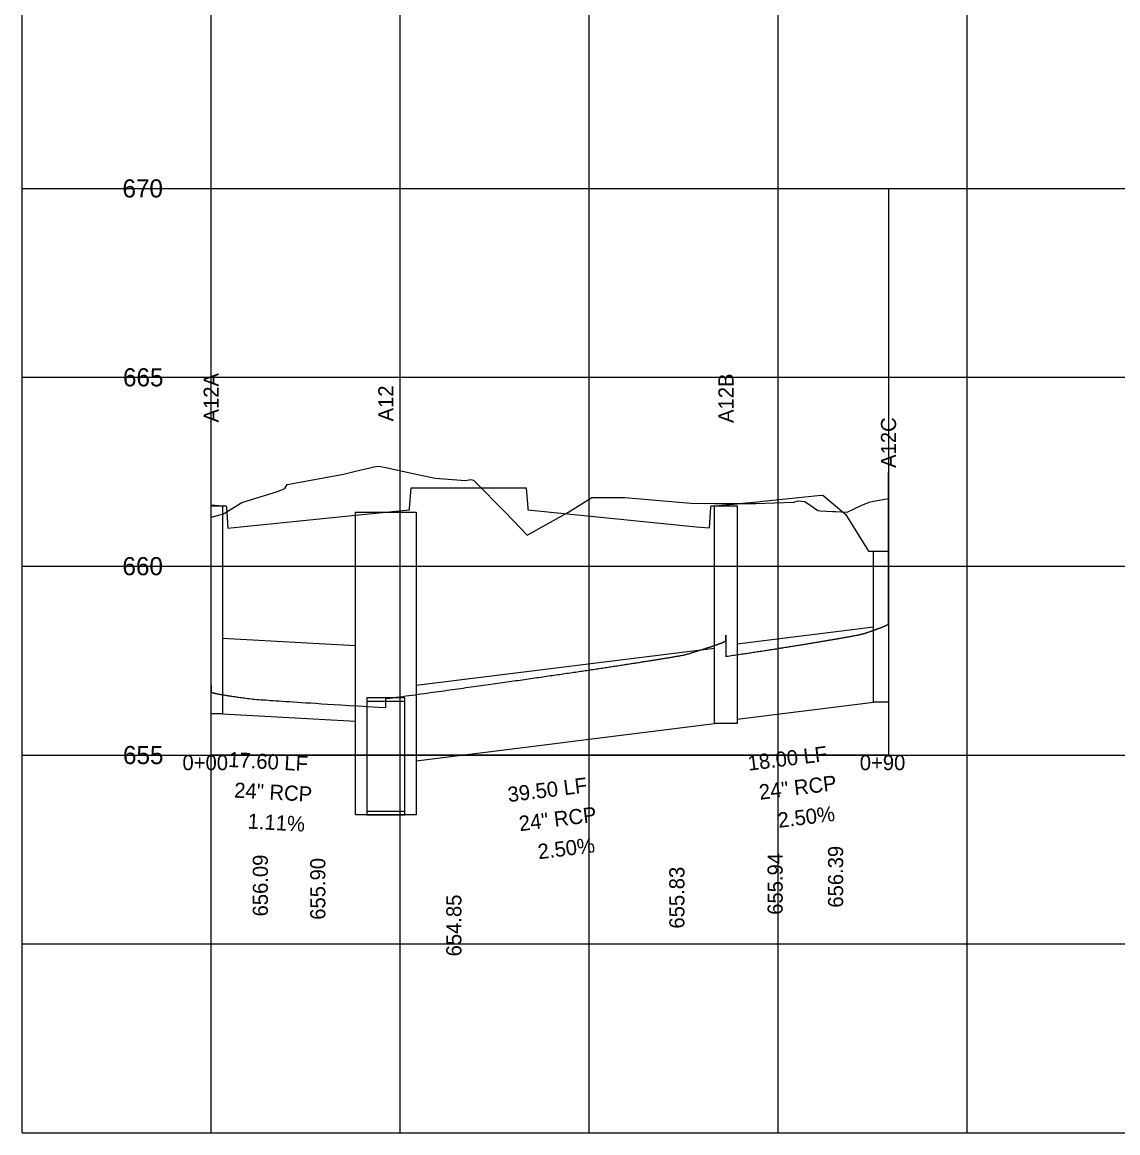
# Model space of a CAD drawing. Extents: x 2252703 to 2264864, y 13787568 to 13790989.
# Drawn here: x 2264413.7 to 2264558.6, y 13789015.9 to 13789162.9 of the extents above; entities that cross this region are included whole.
import ezdxf

# ---------------------------------------------------------------- set-up
doc = ezdxf.new("R2010")
doc.units = 0
for name, color, linetype in [('blank4', 7, 'Continuous'), ('BORD_grid_bottom_major_5int', 7, 'Continuous'), ('D_DRN_PROF_HGL', 7, 'Continuous'), ('D_PROF_1', 7, 'Continuous'), ('D_PROF_NOTES_1', 7, 'Continuous'), ('Default', 7, 'Continuous'), ('Drain_PipeInside', 7, 'Continuous'), ('E_Terrain', 7, 'Continuous'), ('Inlet', 7, 'Continuous'), ('z - Construction', 7, 'Continuous')]:
    doc.layers.add(name, color=color, linetype=linetype)

msp = doc.modelspace()

# ---------------------------------------------------------------- linework, layer by layer
at = {"layer": 'blank4'}
msp.add_lwpolyline([(2264438.67, 13789065.93), (2264438.67, 13789140.93), (2264528.27, 13789140.93), (2264528.27, 13789065.93)], close=True, dxfattribs=at)
at = {"layer": 'BORD_grid_bottom_major_5int'}
for p, q in [((2264413.67, 13789015.93), (2264413.67, 13789315.93)), ((2264438.67, 13789015.93), (2264438.67, 13789315.93)), ((2264463.67, 13789015.93), (2264463.67, 13789315.93)), ((2264488.67, 13789015.93), (2264488.67, 13789315.93)), ((2264513.67, 13789015.93), (2264513.67, 13789315.93)), ((2264538.67, 13789015.93), (2264538.67, 13789315.93)), ((2264413.67, 13789140.93), (2264763.67, 13789140.93)), ((2264413.67, 13789115.93), (2264763.67, 13789115.93)), ((2264413.67, 13789090.93), (2264763.67, 13789090.93)), ((2264413.67, 13789065.93), (2264763.67, 13789065.93)), ((2264413.67, 13789040.93), (2264763.67, 13789040.93)), ((2264413.67, 13789015.93), (2264763.67, 13789015.93))]:
    msp.add_line(p, q, dxfattribs=at)
at = {"layer": 'D_DRN_PROF_HGL'}
for p, q in [((2264506.77, 13789081.82), (2264506.77, 13789078.99)), ((2264461.77, 13789072.22), (2264461.77, 13789073.39))]:
    msp.add_line(p, q, dxfattribs=at)
for points in [[(2264506.77, 13789078.99), (2264506.85, 13789079), (2264507.06, 13789079.03), (2264507.27, 13789079.07), (2264507.47, 13789079.1), (2264507.68, 13789079.13), (2264507.88, 13789079.16), (2264508.09, 13789079.19), (2264508.29, 13789079.22), (2264508.48, 13789079.25), (2264508.68, 13789079.28), (2264508.88, 13789079.31), (2264509.07, 13789079.34), (2264509.27, 13789079.37), (2264509.46, 13789079.39), (2264509.65, 13789079.42), (2264509.84, 13789079.45), (2264510.02, 13789079.48), (2264510.21, 13789079.51), (2264510.4, 13789079.54), (2264510.58, 13789079.56), (2264510.76, 13789079.59), (2264510.94, 13789079.62), (2264511.12, 13789079.65), (2264511.3, 13789079.67), (2264511.48, 13789079.7), (2264511.65, 13789079.73), (2264511.82, 13789079.76), (2264512, 13789079.78), (2264512.17, 13789079.81), (2264512.34, 13789079.83), (2264512.51, 13789079.86), (2264512.68, 13789079.89), (2264512.84, 13789079.91), (2264513.01, 13789079.94), (2264513.17, 13789079.96), (2264513.33, 13789079.99), (2264513.5, 13789080.01), (2264513.66, 13789080.04), (2264513.81, 13789080.06), (2264513.97, 13789080.09), (2264514.13, 13789080.11), (2264514.28, 13789080.14), (2264514.44, 13789080.16), (2264514.59, 13789080.19), (2264514.74, 13789080.21), (2264514.9, 13789080.23), (2264515.05, 13789080.26), (2264515.19, 13789080.28), (2264515.34, 13789080.31), (2264515.49, 13789080.33), (2264515.63, 13789080.35), (2264515.78, 13789080.37), (2264515.92, 13789080.4), (2264516.06, 13789080.42), (2264516.2, 13789080.44), (2264516.34, 13789080.47), (2264516.48, 13789080.49), (2264516.62, 13789080.51), (2264516.76, 13789080.53), (2264516.89, 13789080.55), (2264517.03, 13789080.58), (2264517.16, 13789080.6), (2264517.29, 13789080.62), (2264517.43, 13789080.64), (2264517.56, 13789080.66), (2264517.69, 13789080.68), (2264517.81, 13789080.7), (2264517.94, 13789080.73), (2264518.07, 13789080.75), (2264518.19, 13789080.77), (2264518.32, 13789080.79), (2264518.44, 13789080.81), (2264518.57, 13789080.83), (2264518.69, 13789080.85), (2264518.81, 13789080.87), (2264518.93, 13789080.89), (2264519.05, 13789080.91), (2264519.17, 13789080.93), (2264519.28, 13789080.95), (2264519.4, 13789080.97), (2264519.51, 13789080.99), (2264519.63, 13789081.01), (2264519.74, 13789081.03), (2264519.85, 13789081.04), (2264519.97, 13789081.06), (2264520.08, 13789081.08), (2264520.19, 13789081.1), (2264520.3, 13789081.12), (2264520.4, 13789081.14), (2264520.51, 13789081.16), (2264520.62, 13789081.17), (2264520.72, 13789081.19), (2264520.83, 13789081.21), (2264520.93, 13789081.23), (2264521.03, 13789081.25), (2264521.14, 13789081.26), (2264521.24, 13789081.28), (2264521.34, 13789081.3), (2264521.44, 13789081.32), (2264521.54, 13789081.33), (2264521.63, 13789081.35), (2264521.73, 13789081.37), (2264521.83, 13789081.39), (2264521.92, 13789081.4), (2264522.02, 13789081.42), (2264522.11, 13789081.44), (2264522.2, 13789081.45), (2264522.29, 13789081.47), (2264522.39, 13789081.49), (2264522.48, 13789081.5), (2264522.57, 13789081.52), (2264522.66, 13789081.53), (2264522.74, 13789081.55), (2264522.83, 13789081.57), (2264522.92, 13789081.58), (2264523, 13789081.6), (2264523.09, 13789081.61), (2264523.17, 13789081.63), (2264523.26, 13789081.64), (2264523.34, 13789081.66), (2264523.42, 13789081.67), (2264523.5, 13789081.69), (2264523.58, 13789081.71), (2264523.66, 13789081.72), (2264523.74, 13789081.74), (2264523.82, 13789081.75), (2264523.9, 13789081.76), (2264523.97, 13789081.78), (2264524.05, 13789081.79), (2264524.12, 13789081.81), (2264524.2, 13789081.82), (2264524.27, 13789081.84), (2264524.35, 13789081.85), (2264524.42, 13789081.86), (2264524.49, 13789081.88), (2264524.56, 13789081.89), (2264524.63, 13789081.91), (2264524.7, 13789081.92), (2264524.77, 13789081.93), (2264524.84, 13789081.96), (2264524.9, 13789081.98), (2264524.97, 13789082), (2264525.04, 13789082.02), (2264525.1, 13789082.04), (2264525.17, 13789082.06), (2264525.23, 13789082.08), (2264525.29, 13789082.1), (2264525.36, 13789082.12), (2264525.42, 13789082.15), (2264525.48, 13789082.17), (2264525.54, 13789082.19), (2264525.6, 13789082.21), (2264525.66, 13789082.23), (2264525.72, 13789082.24), (2264525.77, 13789082.26), (2264525.83, 13789082.28), (2264525.89, 13789082.3), (2264525.94, 13789082.32), (2264526, 13789082.34), (2264526.05, 13789082.36), (2264526.1, 13789082.38), (2264526.16, 13789082.4), (2264526.21, 13789082.41), (2264526.26, 13789082.43), (2264526.31, 13789082.45), (2264526.36, 13789082.47), (2264526.41, 13789082.48), (2264526.46, 13789082.5), (2264526.51, 13789082.52), (2264526.56, 13789082.53), (2264526.6, 13789082.55), (2264526.65, 13789082.57), (2264526.7, 13789082.58), (2264526.74, 13789082.6), (2264526.78, 13789082.62), (2264526.83, 13789082.63), (2264526.87, 13789082.65), (2264526.91, 13789082.66), (2264526.95, 13789082.68), (2264527, 13789082.69), (2264527.04, 13789082.71), (2264527.08, 13789082.72), (2264527.12, 13789082.74), (2264527.15, 13789082.75), (2264527.19, 13789082.77), (2264527.23, 13789082.78), (2264527.26, 13789082.8), (2264527.3, 13789082.81), (2264527.34, 13789082.82), (2264527.37, 13789082.84), (2264527.4, 13789082.85), (2264527.44, 13789082.87), (2264527.47, 13789082.88), (2264527.5, 13789082.89), (2264527.53, 13789082.9), (2264527.56, 13789082.92), (2264527.59, 13789082.93), (2264527.62, 13789082.94), (2264527.65, 13789082.95), (2264527.68, 13789082.97), (2264527.71, 13789082.98), (2264527.74, 13789082.99), (2264527.76, 13789083), (2264527.79, 13789083.01), (2264527.81, 13789083.02), (2264527.84, 13789083.03), (2264527.86, 13789083.05), (2264527.88, 13789083.06), (2264527.9, 13789083.07), (2264527.93, 13789083.08), (2264527.95, 13789083.09), (2264527.97, 13789083.1), (2264527.99, 13789083.11), (2264528.01, 13789083.12), (2264528.03, 13789083.13), (2264528.04, 13789083.14), (2264528.06, 13789083.15), (2264528.08, 13789083.15), (2264528.09, 13789083.16), (2264528.11, 13789083.17), (2264528.12, 13789083.18), (2264528.14, 13789083.19), (2264528.15, 13789083.2), (2264528.16, 13789083.21), (2264528.17, 13789083.21), (2264528.18, 13789083.22), (2264528.2, 13789083.23), (2264528.21, 13789083.24), (2264528.21, 13789083.24), (2264528.22, 13789083.25), (2264528.23, 13789083.26), (2264528.24, 13789083.27), (2264528.24, 13789083.27), (2264528.25, 13789083.28), (2264528.26, 13789083.28), (2264528.26, 13789083.29), (2264528.26, 13789083.3), (2264528.27, 13789083.3), (2264528.27, 13789083.31), (2264528.27, 13789083.31), (2264528.27, 13789083.32), (2264528.27, 13789083.32), (2264528.27, 13789103.33)], [(2264461.77, 13789073.39), (2264461.84, 13789073.4), (2264462.28, 13789073.46), (2264462.72, 13789073.52), (2264463.15, 13789073.58), (2264463.57, 13789073.64), (2264464, 13789073.69), (2264464.41, 13789073.75), (2264464.83, 13789073.81), (2264465.24, 13789073.86), (2264465.64, 13789073.92), (2264466.05, 13789073.97), (2264466.45, 13789074.03), (2264466.84, 13789074.08), (2264467.23, 13789074.14), (2264467.62, 13789074.19), (2264468, 13789074.24), (2264468.39, 13789074.3), (2264468.76, 13789074.35), (2264469.14, 13789074.4), (2264469.51, 13789074.45), (2264469.88, 13789074.5), (2264470.24, 13789074.55), (2264470.6, 13789074.6), (2264470.96, 13789074.65), (2264471.31, 13789074.7), (2264471.67, 13789074.75), (2264472.01, 13789074.8), (2264472.36, 13789074.85), (2264472.7, 13789074.9), (2264473.04, 13789074.94), (2264473.38, 13789074.99), (2264473.71, 13789075.04), (2264474.04, 13789075.08), (2264474.37, 13789075.13), (2264474.7, 13789075.18), (2264475.02, 13789075.22), (2264475.34, 13789075.27), (2264475.65, 13789075.31), (2264475.97, 13789075.35), (2264476.28, 13789075.4), (2264476.59, 13789075.44), (2264476.9, 13789075.49), (2264477.2, 13789075.53), (2264477.5, 13789075.57), (2264477.8, 13789075.61), (2264478.1, 13789075.66), (2264478.39, 13789075.7), (2264478.68, 13789075.74), (2264478.97, 13789075.78), (2264479.26, 13789075.82), (2264479.54, 13789075.86), (2264479.82, 13789075.9), (2264480.1, 13789075.94), (2264480.38, 13789075.98), (2264480.65, 13789076.02), (2264480.93, 13789076.06), (2264481.2, 13789076.1), (2264481.46, 13789076.14), (2264481.73, 13789076.18), (2264481.99, 13789076.21), (2264482.26, 13789076.25), (2264482.52, 13789076.29), (2264482.77, 13789076.33), (2264483.03, 13789076.36), (2264483.28, 13789076.4), (2264483.53, 13789076.44), (2264483.78, 13789076.47), (2264484.03, 13789076.51), (2264484.28, 13789076.54), (2264484.52, 13789076.58), (2264484.76, 13789076.61), (2264485, 13789076.65), (2264485.24, 13789076.68), (2264485.47, 13789076.72), (2264485.71, 13789076.75), (2264485.94, 13789076.79), (2264486.17, 13789076.82), (2264486.4, 13789076.85), (2264486.62, 13789076.89), (2264486.85, 13789076.92), (2264487.07, 13789076.95), (2264487.29, 13789076.99), (2264487.51, 13789077.02), (2264487.73, 13789077.05), (2264487.94, 13789077.08), (2264488.16, 13789077.11), (2264488.37, 13789077.14), (2264488.58, 13789077.18), (2264488.79, 13789077.21), (2264489, 13789077.24), (2264489.2, 13789077.27), (2264489.41, 13789077.3), (2264489.61, 13789077.33), (2264489.81, 13789077.36), (2264490.01, 13789077.39), (2264490.21, 13789077.42), (2264490.4, 13789077.45), (2264490.6, 13789077.48), (2264490.79, 13789077.51), (2264490.98, 13789077.54), (2264491.17, 13789077.56), (2264491.36, 13789077.59), (2264491.54, 13789077.62), (2264491.73, 13789077.65), (2264491.91, 13789077.68), (2264492.1, 13789077.71), (2264492.28, 13789077.73), (2264492.46, 13789077.76), (2264492.63, 13789077.79), (2264492.81, 13789077.81), (2264492.99, 13789077.84), (2264493.16, 13789077.87), (2264493.33, 13789077.9), (2264493.5, 13789077.92), (2264493.67, 13789077.95), (2264493.84, 13789077.97), (2264494.01, 13789078), (2264494.17, 13789078.03), (2264494.34, 13789078.05), (2264494.5, 13789078.08), (2264494.66, 13789078.1), (2264494.82, 13789078.13), (2264494.98, 13789078.15), (2264495.14, 13789078.18), (2264495.29, 13789078.2), (2264495.45, 13789078.22), (2264495.6, 13789078.25), (2264495.75, 13789078.27), (2264495.9, 13789078.3), (2264496.05, 13789078.32), (2264496.2, 13789078.34), (2264496.35, 13789078.37), (2264496.5, 13789078.39), (2264496.64, 13789078.41), (2264496.78, 13789078.44), (2264496.93, 13789078.46), (2264497.07, 13789078.48), (2264497.21, 13789078.5), (2264497.35, 13789078.53), (2264497.48, 13789078.55), (2264497.62, 13789078.57), (2264497.75, 13789078.59), (2264497.89, 13789078.61), (2264498.02, 13789078.64), (2264498.15, 13789078.66), (2264498.28, 13789078.68), (2264498.41, 13789078.7), (2264498.54, 13789078.72), (2264498.67, 13789078.74), (2264498.79, 13789078.76), (2264498.92, 13789078.78), (2264499.04, 13789078.8), (2264499.17, 13789078.82), (2264499.29, 13789078.84), (2264499.41, 13789078.86), (2264499.53, 13789078.88), (2264499.65, 13789078.9), (2264499.76, 13789078.92), (2264499.88, 13789078.94), (2264499.99, 13789078.96), (2264500.11, 13789078.98), (2264500.22, 13789079), (2264500.33, 13789079.02), (2264500.44, 13789079.04), (2264500.55, 13789079.06), (2264500.66, 13789079.08), (2264500.77, 13789079.09), (2264500.88, 13789079.11), (2264500.98, 13789079.13), (2264501.09, 13789079.15), (2264501.19, 13789079.17), (2264501.29, 13789079.19), (2264501.39, 13789079.22), (2264501.49, 13789079.25), (2264501.59, 13789079.28), (2264501.69, 13789079.31), (2264501.79, 13789079.34), (2264501.88, 13789079.37), (2264501.98, 13789079.39), (2264502.07, 13789079.42), (2264502.17, 13789079.45), (2264502.26, 13789079.48), (2264502.35, 13789079.51), (2264502.44, 13789079.54), (2264502.53, 13789079.56), (2264502.62, 13789079.59), (2264502.71, 13789079.62), (2264502.79, 13789079.64), (2264502.88, 13789079.67), (2264502.97, 13789079.7), (2264503.05, 13789079.72), (2264503.13, 13789079.75), (2264503.21, 13789079.77), (2264503.29, 13789079.8), (2264503.37, 13789079.82), (2264503.45, 13789079.85), (2264503.53, 13789079.87), (2264503.61, 13789079.9), (2264503.68, 13789079.92), (2264503.76, 13789079.94), (2264503.83, 13789079.97), (2264503.91, 13789079.99), (2264503.98, 13789080.01), (2264504.05, 13789080.04), (2264504.12, 13789080.06), (2264504.19, 13789080.08), (2264504.26, 13789080.1), (2264504.33, 13789080.13), (2264504.39, 13789080.15), (2264504.46, 13789080.17), (2264504.52, 13789080.19), (2264504.59, 13789080.21), (2264504.65, 13789080.23), (2264504.71, 13789080.25), (2264504.78, 13789080.27), (2264504.84, 13789080.29), (2264504.9, 13789080.31), (2264504.95, 13789080.33), (2264505.01, 13789080.35), (2264505.07, 13789080.37), (2264505.12, 13789080.39), (2264505.18, 13789080.41), (2264505.23, 13789080.43), (2264505.29, 13789080.45), (2264505.34, 13789080.46), (2264505.39, 13789080.48), (2264505.44, 13789080.5), (2264505.49, 13789080.52), (2264505.54, 13789080.53), (2264505.59, 13789080.55), (2264505.63, 13789080.57), (2264505.68, 13789080.58), (2264505.72, 13789080.6), (2264505.77, 13789080.62), (2264505.81, 13789080.63), (2264505.85, 13789080.65), (2264505.89, 13789080.66), (2264505.93, 13789080.68), (2264505.97, 13789080.69), (2264506.01, 13789080.71), (2264506.05, 13789080.72), (2264506.09, 13789080.74), (2264506.12, 13789080.75), (2264506.16, 13789080.76), (2264506.19, 13789080.78), (2264506.22, 13789080.79), (2264506.25, 13789080.8), (2264506.29, 13789080.82), (2264506.32, 13789080.83), (2264506.35, 13789080.84), (2264506.37, 13789080.85), (2264506.4, 13789080.86), (2264506.43, 13789080.88), (2264506.45, 13789080.89), (2264506.48, 13789080.9), (2264506.5, 13789080.91), (2264506.52, 13789080.92), (2264506.55, 13789080.93), (2264506.57, 13789080.94), (2264506.59, 13789080.95), (2264506.6, 13789080.96), (2264506.62, 13789080.97), (2264506.64, 13789080.98), (2264506.65, 13789080.99), (2264506.67, 13789081), (2264506.68, 13789081.01), (2264506.7, 13789081.01), (2264506.71, 13789081.02), (2264506.72, 13789081.03), (2264506.73, 13789081.04), (2264506.74, 13789081.04), (2264506.75, 13789081.05), (2264506.75, 13789081.06), (2264506.76, 13789081.06), (2264506.76, 13789081.07), (2264506.77, 13789081.08), (2264506.77, 13789081.08), (2264506.77, 13789081.09), (2264506.77, 13789081.09), (2264506.77, 13789081.82)], [(2264438.67, 13789075.17), (2264438.67, 13789074.3), (2264438.67, 13789074.29), (2264438.67, 13789074.29), (2264438.67, 13789074.28), (2264438.68, 13789074.28), (2264438.68, 13789074.27), (2264438.69, 13789074.27), (2264438.69, 13789074.26), (2264438.7, 13789074.26), (2264438.71, 13789074.25), (2264438.72, 13789074.24), (2264438.73, 13789074.24), (2264438.75, 13789074.23), (2264438.76, 13789074.22), (2264438.78, 13789074.22), (2264438.8, 13789074.21), (2264438.82, 13789074.2), (2264438.84, 13789074.2), (2264438.86, 13789074.19), (2264438.89, 13789074.18), (2264438.92, 13789074.17), (2264438.94, 13789074.16), (2264438.97, 13789074.16), (2264439.01, 13789074.15), (2264439.04, 13789074.14), (2264439.08, 13789074.13), (2264439.11, 13789074.12), (2264439.15, 13789074.11), (2264439.2, 13789074.1), (2264439.24, 13789074.09), (2264439.29, 13789074.08), (2264439.34, 13789074.07), (2264439.39, 13789074.06), (2264439.44, 13789074.05), (2264439.5, 13789074.04), (2264439.56, 13789074.03), (2264439.62, 13789074.01), (2264439.68, 13789074), (2264439.75, 13789073.99), (2264439.82, 13789073.98), (2264439.89, 13789073.96), (2264439.97, 13789073.95), (2264440.05, 13789073.94), (2264440.13, 13789073.92), (2264440.22, 13789073.91), (2264440.31, 13789073.89), (2264440.4, 13789073.88), (2264440.5, 13789073.86), (2264440.6, 13789073.85), (2264440.7, 13789073.83), (2264440.81, 13789073.81), (2264440.92, 13789073.79), (2264441.04, 13789073.78), (2264441.16, 13789073.76), (2264441.29, 13789073.74), (2264441.42, 13789073.72), (2264441.56, 13789073.7), (2264441.7, 13789073.68), (2264441.85, 13789073.66), (2264442.01, 13789073.63), (2264442.17, 13789073.61), (2264442.33, 13789073.59), (2264442.51, 13789073.56), (2264442.69, 13789073.54), (2264442.87, 13789073.51), (2264443.07, 13789073.49), (2264443.27, 13789073.46), (2264443.48, 13789073.43), (2264443.71, 13789073.4), (2264443.94, 13789073.37), (2264444.18, 13789073.34), (2264444.43, 13789073.32), (2264444.69, 13789073.3), (2264444.96, 13789073.28), (2264445.25, 13789073.26), (2264445.55, 13789073.24), (2264445.86, 13789073.22), (2264446.19, 13789073.19), (2264446.53, 13789073.17), (2264446.89, 13789073.14), (2264447.27, 13789073.12), (2264447.67, 13789073.09), (2264448.09, 13789073.06), (2264448.54, 13789073.03), (2264449.01, 13789073), (2264449.51, 13789072.97), (2264450.04, 13789072.93), (2264450.6, 13789072.9), (2264451.2, 13789072.86), (2264451.84, 13789072.82), (2264452.53, 13789072.78), (2264453.27, 13789072.73), (2264454.07, 13789072.68), (2264454.94, 13789072.63), (2264455.88, 13789072.57), (2264456.92, 13789072.51), (2264458.07, 13789072.44), (2264459.35, 13789072.36), (2264460.79, 13789072.28), (2264461.77, 13789072.22)]]:
    msp.add_lwpolyline(points, dxfattribs=at)
at = {"layer": 'D_PROF_1'}
msp.add_lwpolyline([(2264438.67, 13789099.05), (2264440.14, 13789098.9), (2264440.17, 13789098.9), (2264440.17, 13789098.9), (2264440.18, 13789098.9), (2264440.66, 13789098.9), (2264440.68, 13789098.69), (2264440.89, 13789095.98), (2264442.56, 13789096.15), (2264457.77, 13789097.67), (2264457.77, 13789097.67), (2264461.77, 13789098.07), (2264461.77, 13789098.07), (2264464.9, 13789098.38), (2264464.91, 13789098.58), (2264465.12, 13789101.3), (2264465.16, 13789101.3), (2264465.65, 13789101.3), (2264465.77, 13789101.3), (2264465.77, 13789101.3), (2264478.81, 13789101.31), (2264479.81, 13789101.31), (2264480.3, 13789101.31), (2264480.33, 13789101.31), (2264480.54, 13789098.59), (2264480.56, 13789098.39), (2264502.88, 13789096.16), (2264504.57, 13789095.99), (2264504.78, 13789098.7), (2264504.8, 13789098.91), (2264505.27, 13789098.91), (2264505.27, 13789098.91), (2264505.28, 13789098.91), (2264505.32, 13789098.91), (2264506.77, 13789099.05), (2264506.77, 13789099.05), (2264508.27, 13789099.2), (2264508.27, 13789099.2), (2264509.33, 13789099.31), (2264509.57, 13789099.33), (2264518.93, 13789100.27), (2264519.57, 13789100.33), (2264522.37, 13789098), (2264522.57, 13789097.83), (2264525.4, 13789093.25), (2264525.62, 13789092.91), (2264526.27, 13789092.91), (2264526.27, 13789092.91), (2264527.94, 13789092.91), (2264528.12, 13789092.91), (2264528.27, 13789092.91)], dxfattribs=at)
at = {"layer": 'Drain_PipeInside'}
for p, q in [((2264508.27, 13789080.66), (2264526.27, 13789082.91)), ((2264440.17, 13789081.4), (2264457.77, 13789080.42)), ((2264465.77, 13789075.16), (2264505.27, 13789080.09)), ((2264508.27, 13789070.66), (2264526.27, 13789072.91)), ((2264440.17, 13789071.4), (2264457.77, 13789070.42)), ((2264465.77, 13789065.16), (2264505.27, 13789070.09))]:
    msp.add_line(p, q, dxfattribs=at)
for points in [[(2264459.27, 13789058.51), (2264464.27, 13789058.51), (2264464.27, 13789073.51), (2264459.27, 13789073.51)], [(2264459.27, 13789058.01), (2264464.27, 13789058.01), (2264464.27, 13789073.01), (2264459.27, 13789073.01)]]:
    msp.add_lwpolyline(points, close=True, dxfattribs=at)
at = {"layer": 'E_Terrain'}
msp.add_lwpolyline([(2264438.67, 13789097.4), (2264440.17, 13789097.82), (2264440.17, 13789097.82), (2264440.23, 13789097.83), (2264442.72, 13789099.37), (2264447.45, 13789100.82), (2264448.42, 13789101.2), (2264448.7, 13789101.76), (2264456.16, 13789103.11), (2264457.77, 13789103.5), (2264457.77, 13789103.5), (2264459.65, 13789103.96), (2264460.17, 13789104.07), (2264460.83, 13789104.19), (2264461.77, 13789103.98), (2264461.77, 13789103.98), (2264465.77, 13789103.11), (2264465.77, 13789103.11), (2264468.3, 13789102.56), (2264472.29, 13789102.29), (2264473, 13789102.41), (2264473.37, 13789102.3), (2264477.65, 13789097.97), (2264480.48, 13789095.02), (2264485.86, 13789098.02), (2264489.03, 13789100.02), (2264493.37, 13789100.02), (2264502.14, 13789099.25), (2264505.27, 13789099.24), (2264505.27, 13789099.24), (2264506.77, 13789099.24), (2264506.77, 13789099.24), (2264508.27, 13789099.24), (2264508.27, 13789099.24), (2264510.72, 13789099.23), (2264515.73, 13789099.39), (2264516.31, 13789099.59), (2264517.18, 13789099.5), (2264517.89, 13789098.99), (2264518.91, 13789098.29), (2264519.22, 13789098.27), (2264520.92, 13789098.17), (2264521.31, 13789098.15), (2264521.99, 13789098.11), (2264522.78, 13789098.07), (2264524.66, 13789098.94), (2264525.69, 13789099.42), (2264526.27, 13789099.53), (2264526.27, 13789099.53), (2264528.27, 13789099.91)], dxfattribs=at)
at = {"layer": 'Inlet'}
for points in [[(2264438.67, 13789098.9), (2264440.17, 13789098.9), (2264440.17, 13789071.4), (2264438.67, 13789071.4)], [(2264505.27, 13789098.91), (2264508.27, 13789098.91), (2264508.27, 13789070.09), (2264505.27, 13789070.09)], [(2264457.77, 13789098.07), (2264465.77, 13789098.07), (2264465.77, 13789058.01), (2264457.77, 13789058.01)], [(2264526.27, 13789092.91), (2264528.27, 13789092.91), (2264528.27, 13789072.91), (2264526.27, 13789072.91)]]:
    msp.add_lwpolyline(points, close=True, dxfattribs=at)
at = {"layer": 'z - Construction'}
for p, q in [((2264438.67, 13789115.93), (2264528.27, 13789115.93)), ((2264438.67, 13789090.93), (2264528.27, 13789090.93))]:
    msp.add_line(p, q, dxfattribs=at)

# ---------------------------------------------------------------- texts
at = {"layer": 'D_PROF_NOTES_1'}
for s, rotation, p in [('A12A', 90, (2264439.67, 13789109.95)), ('A12B', 90, (2264507.77, 13789109.89)), ('A12', 90, (2264462.77, 13789110.09)), ('A12C', 90, (2264529.27, 13789103.94)), ('17.60 LF', 356.8292, (2264440.88, 13789064.36)), ('18.00 LF', 7.125, (2264509.77, 13789063.85)), ('24" RCP', 7.125, (2264511.27, 13789060.01)), ('24" RCP', 356.8292, (2264441.67, 13789060.31)), ('39.50 LF', 7.125, (2264478.02, 13789059.69)), ('24" RCP', 7.125, (2264479.51, 13789055.85)), ('2.50%', 7.125, (2264513.75, 13789056.29)), ('1.11%', 356.8292, (2264443.45, 13789056.2)), ('2.50%', 7.125, (2264482, 13789052.13)), ('655.94', 90, (2264514.27, 13789044.79)), ('656.39', 90, (2264522.27, 13789045.73)), ('656.09', 90, (2264446.17, 13789044.57)), ('655.90', 90, (2264453.77, 13789044.13)), ('655.83', 90, (2264501.27, 13789042.96)), ('654.85', 90, (2264471.77, 13789039.28))]:
    msp.add_text(s, height=2, rotation=rotation, dxfattribs=at).set_placement(p)
at = {"layer": 'Default'}
for s, height, p in [('670', 2.4, (2264426.93, 13789139.73)), ('665', 2.4, (2264427, 13789114.73)), ('660', 2.4, (2264426.93, 13789089.73)), ('655', 2.4, (2264427, 13789064.73)), ('0+00', 2, (2264434.87, 13789063.93)), ('0+90', 2, (2264524.47, 13789063.93))]:
    msp.add_text(s, height=height, dxfattribs=at).set_placement(p)

doc.saveas('drawing.dxf')
